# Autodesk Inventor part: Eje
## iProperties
Shininess: 64.0
Length Units: 11272
Angle Units: 11279
Time Units: 11290
Mass Units: 11286
Length Display Precision: 3
Angle Display Precision: 2
Compacted: True
Part Number: Eje
Document SubType Name: Modeling
Created: 2005-06
Designer: Alek
Manufacturer: Standard
Standards Organization: Custom
Density: 0.0
Volumn: 0.0
Area: 0.0
PropertySet Name: Model Information
Control State: 0
Master: False
Checked Out: False
Author: Alek
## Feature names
1. Revolution1
2. Extrusion1
3. Hole1
4. Extrusion4
5. Chamfer1
